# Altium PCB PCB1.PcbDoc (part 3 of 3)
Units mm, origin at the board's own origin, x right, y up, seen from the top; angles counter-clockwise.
Board outline 131.32 x 71.5 mm, 4 copper layers (Top Layer, Layer 1, Layer 2, Bottom Layer), stack 0.603 mm thick; 122 components, 132 nets, 671 pads, 444 vias.
Unrouted connection lines stored in the file: 1.
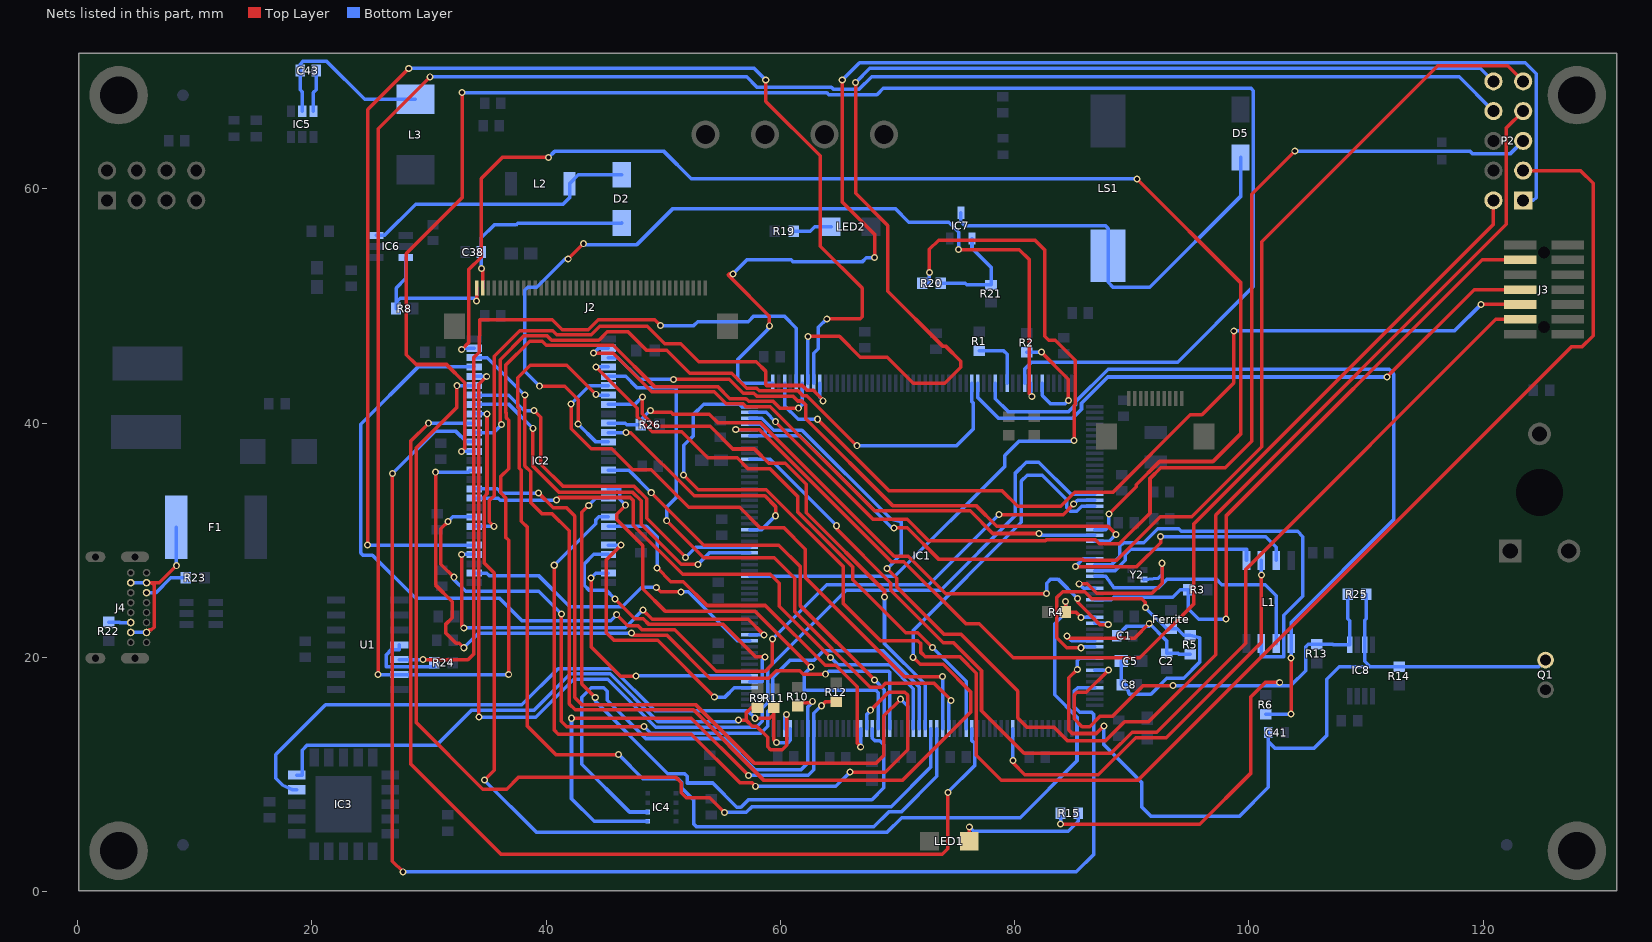
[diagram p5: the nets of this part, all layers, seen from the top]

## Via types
v1: diameter 0.6, hole 0.35, Top Layer to Bottom Layer, 444 vias

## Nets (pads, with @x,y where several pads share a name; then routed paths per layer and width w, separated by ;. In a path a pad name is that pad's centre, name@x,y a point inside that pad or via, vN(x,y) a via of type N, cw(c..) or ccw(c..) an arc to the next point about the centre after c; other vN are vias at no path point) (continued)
NetC41_2: C41.2 IC1.44 IC8.3 Q1.2 R14.2 R25.2 | length 72.5
  Top Layer w0.3: v1(85.344,18.974) 84.626,18.256 84.626,13.808 84.927,13.507 86.973,13.507 v1(87.613,14.148)
  Bottom Layer w0.3: v1(85.344,18.974) 85.344,19.716 85.547,19.919 IC1.44@86.841,19.919 ; v1(87.613,14.148) 87.613,12.564 90.83,9.347 90.83,7.239 91.643,6.426 99.162,6.426 101.652,8.917 101.652,12.826 ; C41.2@101.652,13.589 101.652,12.826 ; R25.2@110.02,25.4 110.02,23.292 109.893,23.165 IC8.3@109.893,21.09 109.893,19.66 110.338,19.215 ; Q1.2@125.316,19.779 124.752,19.215 R14.2@112.838,19.215 110.338,19.215 ; 101.652,12.826 102.21,12.268 105.562,12.268 106.629,13.335 106.629,18.136 107.709,19.215 110.338,19.215
NetC43_1: C43.1 IC5.5 L3.1 | length 15.4
  Bottom Layer w0.3: IC5.5@19.177,66.631 19.177,68.275 18.995,68.457 C43.1@18.995,70.104 18.995,70.637 19.274,70.917 21.237,70.917 24.511,67.643 L3.1@28.829,67.643
NetC43_2: C43.2 IC5.6 | length 3.6
  Bottom Layer w0.3: IC5.6@20.127,66.631 20.127,68.224 20.375,68.472 C43.2@20.375,70.104
NetD2_2: D2.2 IC6.3 L2.2 | length 23.8
  Bottom Layer w0.3: IC6.3@25.514,56.035 26.204,56.035 28.871,58.702 41.441,58.702 41.997,59.258 L2.2@41.997,60.452 42.744,61.199 D2.2@46.449,61.199
NetD5_2: D5.2 IC7.3 LS1.2 | length 36.2
  Bottom Layer w0.3: IC7.3@75.405,57.963 75.405,57.226 75.761,56.871 87.724,56.871 87.978,56.617 LS1.2@87.978,54.288 87.978,52.025 88.392,51.611 91.542,51.611 99.281,59.35 D5.2@99.281,62.687
NetF1_1: F1.1 J4.A4 J4.A9 J4.B4 J4.B9 | length 13.9
  Top Layer w0.3: J4.A9@5.884,22.132 6.104,22.352 6.299,22.352 6.528,22.581 6.528,26.153 6.299,26.382 ; J4.A4@5.884,26.382 6.299,26.382 ; v1(8.426,27.832) 6.976,26.382 6.299,26.382
  Bottom Layer w0.3: J4.B4@4.534,22.132 J4.A9@5.884,22.132 ; J4.B9@4.534,26.382 J4.A4@5.884,26.382 ; v1(8.426,27.832) F1.1@8.426,31.115
NetIC1_32: IC1.32 Y2.3 | length 13.6
  Top Layer w0.3: v1(85.507,26.289) 86.204,26.289 87.017,25.476 91.719,25.476 92.583,26.34 v1(92.583,28.042)
  Bottom Layer w0.3: v1(85.507,26.289) 85.877,25.919 IC1.32@86.841,25.919 ; Y2.3@91.02,26.651 92.253,26.756 92.583,27.086 v1(92.583,28.042)
NetIC1_34: IC1.34 J3.12 R3.1 | length 56.5
  Top Layer w0.3: v1(98.044,23.266) 98.044,32.08 119.906,53.942 J3.12@123.151,53.942
  Bottom Layer w0.3: IC1.34@86.841,24.919 88.24,24.919 88.474,25.153 93.505,25.153 94.132,25.781 R3.1@94.831,25.781 94.831,24.143 95.707,23.266 v1(98.044,23.266)
NetIC1_46: IC1.46 IC8.1 R13.2 R15.1 R25.1 | length 68
  Top Layer w0.3: v1(83.922,5.766) 95.809,5.766 100.134,10.091 100.134,16.601 101.397,17.863 v1(102.623,17.863) ; v1(88.011,18.919) 86.111,17.019 85.306,17.019 85.076,16.789 85.076,14.771 85.75,14.097 86.411,14.097 87.274,14.96 88.326,14.96 90.969,17.602 v1(93.523,17.602)
  Bottom Layer w0.3: v1(83.922,5.766) 83.926,5.77 R15.1@83.926,6.698 ; IC1.46@86.841,18.919 v1(88.011,18.919) ; v1(93.523,17.602) v1@102.623,17.602 ; v1(102.623,17.863) v1@102.623,17.602 ; R25.1@108.42,25.4 108.42,23.312 108.593,23.139 IC8.1@108.593,21.09 107.193,21.09 107.163,21.12 R13.2@105.791,21.12 105.054,21.12 104.851,20.917 104.851,18.872 103.581,17.602 v1@102.623,17.602
NetIC1_97: IC1.97 IC4.4 R12.2 | length 44.2
  Top Layer w0.3: v1(42.164,14.808) 52.4,14.808 v1(57.277,9.931) ; v1(63.5,15.875) 63.843,16.218 R12.2@64.77,16.218
  Bottom Layer w0.3: v1(42.164,14.808) 42.164,7.95 44.108,6.006 IC4.4@48.678,6.006 ; v1(57.277,9.931) 62.382,9.931 62.853,10.402 62.853,15.228 v1(63.5,15.875)
NetIC1_98: IC1.98 IC4.3 R10.1 | length 43.1
  Top Layer w0.3: R10.1@61.468,15.837 61.768,16.137 62.538,16.137 62.657,16.256 v1(62.738,16.256)
  Bottom Layer w0.3: IC4.3@48.678,6.806 47.117,6.806 43.028,10.895 43.028,16.586 43.84,17.399 44.933,17.399 45.229,17.103 45.229,16.344 48.493,13.08 55.203,13.08 57.858,10.425 61.759,10.425 62.353,11.02 IC1.98@62.353,13.931 62.353,15.79 62.738,16.175 v1(62.738,16.256)
NetIC1_101: IC1.101 IC3.9 R11.2 | length 57
  Top Layer w0.3: v1(57.836,14.808) 59.08,14.808 59.436,15.164 ; R11.2@59.436,15.71 59.436,15.164 ; v1(59.665,12.725) 59.436,12.954 59.436,15.164
  Bottom Layer w0.3: IC3.9@18.7,8.71 18.339,8.71 17.475,9.119 16.916,9.677 16.916,11.709 21.167,15.96 37.927,15.96 41.015,19.047 45.696,19.047 49.274,15.469 57.175,15.469 v1(57.836,14.808) ; v1(59.665,12.725) 60.65,12.725 60.853,12.929 IC1.101@60.853,13.931
NetIC1_102: IC1.102 IC3.10 R9.1 | length 55.8
  Top Layer w0.3: v1(56.423,14.656) 57.099,14.656 ; R9.1@58.039,15.71 57.506,15.71 57.099,15.304 57.099,14.656 ; v1(60.528,15.113) 60.528,12.497 60.147,12.116 59.157,12.116 58.906,12.366 58.906,13.179 57.955,14.13 57.583,14.13 57.099,14.615 57.099,14.656
  Bottom Layer w0.3: IC3.10@18.7,9.96 19.177,9.96 19.177,12.09 19.609,12.522 30.658,12.522 33.645,15.51 38.975,15.51 42.062,18.597 45.458,18.597 49.552,14.503 56.423,14.503 v1(56.423,14.656) ; IC1.102@60.353,13.931 60.353,14.938 v1(60.528,15.113)
NetIC1_127: IC1.127 R20.1 | length 64.8
  Top Layer w0.3: v1(72.72,52.857) 72.72,54.839 73.508,55.626 81.737,55.626 82.575,54.788 82.575,47.422 82.906,47.092 83.464,47.092 85.182,45.374 85.182,41.621 85.065,41.504 v1(85.065,38.506)
  Bottom Layer w0.3: IC1.127@57.365,26.919 69.769,26.919 79.146,36.297 79.146,37.236 80.386,38.476 85.034,38.476 v1(85.065,38.506) ; R20.1@72.098,51.943 72.72,51.943 v1(72.72,52.857)
NetIC1_151: IC1.151 IC1.153 P2.9 | length 100.8
  Top Layer w0.3: v1(69.698,31.064) 70.831,31.064 73.533,28.362 85.788,28.362 85.855,28.296 88.697,28.296 92.414,32.012 95.127,32.012 101.092,37.978 101.092,55.474 116.129,70.51 122.083,70.51 P2.9@123.411,69.182
  Bottom Layer w0.3: IC1.151@57.365,38.919 58.682,38.919 ; IC1.153@57.365,39.919 58.276,39.919 58.725,39.47 58.725,38.962 58.682,38.919 ; v1(69.698,31.064) 69.496,31.064 61.641,38.919 58.682,38.919
NetIC1_152: IC1.152 P2.2 | length 95.3
  Top Layer w0.3: v1(56.185,39.446) 58.217,39.446 69.479,28.184 70.517,28.184 75.839,22.863 76.975,22.863 79.868,19.969 90.673,19.969 95.304,24.599 95.304,31.423 120.871,56.99 P2.2@120.871,59.022
  Bottom Layer w0.3: v1(56.185,39.446) 56.212,39.419 IC1.152@57.365,39.419
NetIC1_154: IC1.154 P2.7 | length 117.3
  Top Layer w0.3: v1(69.113,27.584) 69.943,26.754 69.943,26.018 73.998,21.963 75.435,21.963 80.264,17.133 80.264,14.834 81.077,14.021 83.383,14.021 84.497,12.907 87.774,12.907 89.378,14.51 91.425,14.51 97.155,20.24 97.155,32.156 121.971,56.972 121.971,65.202 P2.7@123.411,66.642
  Bottom Layer w0.3: IC1.154@57.365,40.419 58.412,40.419 59.424,39.407 61.837,39.407 69.445,31.799 70.323,31.58 70.323,28.794 v1(69.113,27.584)
NetIC1_155: IC1.155 P2.5 | length 99.2
  Top Layer w0.3: v1(59.569,40.125) 67.901,31.793 70.815,31.793 72.626,29.982 82.626,29.982 82.693,30.048 86.893,30.048 87.228,29.713 88.94,29.713 91.55,32.324 91.55,35.279 92.458,36.186 97.964,36.186 100.228,38.451 100.228,59.538 v1(103.911,63.221)
  Bottom Layer w0.3: IC1.155@57.365,40.919 58.776,40.919 v1(59.569,40.125) ; v1(103.911,63.221) 118.872,63.221 119.075,63.017 122.326,63.017 P2.5@123.411,64.102
NetIC1_156: IC1.156 P2.3 | length 140.7
  Top Layer w0.3: v1(51.74,35.56) 52.984,34.315 58.801,34.315 65.38,27.737 65.38,24.587 68.539,21.428 71.73,21.428 72,21.158 72,20.422 72.375,20.046 75.331,20.046 76.716,18.661 76.716,11.651 78.842,9.525 90.526,9.525 127.508,46.507 128.422,46.507 129.388,47.473 129.388,60.477 128.303,61.562 P2.3@123.411,61.562
  Bottom Layer w0.3: v1(51.74,35.56) 51.74,38.1 52.578,38.938 52.578,40.742 53.442,41.605 56.507,41.605 56.693,41.419 IC1.156@57.365,41.419
NetIC1_157: IC1.157 P2.1 | length 116.2
  Top Layer w0.3: v1(55.939,52.739) 55.618,52.739 55.533,52.654 55.694,52.493 59.061,49.126 v1(59.061,48.313) ; v1(65.278,69.291) 65.278,58.877 68.047,56.109 v1(68.047,54.127)
  Bottom Layer w0.3: v1(55.939,52.739) 57.145,53.944 60.924,53.944 61.107,53.761 66.965,53.761 67.332,54.127 v1(68.047,54.127) ; v1(59.061,48.313) 59.061,48.232 58.918,48.089 58.918,47.996 56.337,45.415 56.337,43.815 56.744,43.409 59.353,43.409 IC1.157@59.353,43.407 ; v1(65.278,69.291) 66.751,70.764 123.571,70.764 124.511,69.825 124.511,59.258 124.275,59.022 P2.1@123.411,59.022
NetIC1_161: IC1.161 U1.5 | length 68.7
  Top Layer w0.3: v1(29.489,19.812) 33.325,19.812 33.8,20.287 33.8,45.571 34.276,46.046 34.341,48.844 40.507,48.844 41.361,47.99 43.607,47.99 44.461,48.844 49.267,48.844 v1(49.775,48.336)
  Bottom Layer w0.3: U1.5@27.465,19.812 v1(29.489,19.812) ; v1(49.775,48.336) 52.603,48.336 52.939,48.672 57.251,48.672 57.727,49.148 60.321,49.148 61.353,48.117 IC1.161@61.353,43.407
NetIC1_162: IC1.162 P2.8 U1.6 | length 214.5
  Top Layer w0.3: v1(25.654,18.542) 25.654,65.126 v1(30.099,69.571) ; v1(36.805,18.542) 36.805,29.997 36.535,30.267 36.535,33.639 36.128,34.046 36.128,35.447 36.8,36.119 36.8,40.263 36.576,40.488 36.576,40.901 36.532,40.945 36.532,44.94 38.588,46.996 39.655,46.996 40.011,46.64 45.74,46.64 49.251,43.129 54.643,43.129 55.678,42.093 57.059,42.093 57.286,41.866 59.368,41.866 59.959,41.275 v1(61.544,41.275)
  Bottom Layer w0.3: v1(25.654,18.542) U1.6@27.465,18.542 v1(36.805,18.542) ; v1(30.099,69.571) 57.118,69.571 57.998,68.691 64.357,68.691 64.561,68.488 66.7,68.488 67.783,69.571 117.942,69.571 P2.8@120.871,66.642 ; v1(61.544,41.275) 61.853,41.584 IC1.162@61.853,43.407
NetIC1_163: IC1.163 P2.10 | length 102.9
  Top Layer w0.3: v1(62.353,47.415) 65.041,47.415 66.819,45.637 69.113,45.637 71.341,43.409 74.016,43.409 75.387,44.78 75.387,45.288 74.092,46.584 73.838,46.584 69.164,51.257 69.164,56.871 66.421,59.614 v1(66.421,69.088)
  Bottom Layer w0.3: IC1.163@62.353,43.407 v1(62.353,47.415) ; v1(66.421,69.088) 67.64,70.307 119.746,70.307 P2.10@120.871,69.182
NetIC1_197: IC1.197 R1.1 | length 5
  Bottom Layer w0.3: R1.1@76.962,46.19 79.045,46.19 79.353,45.882 IC1.197@79.353,43.407
NetIC1_203: IC1.203 R2.2 | length 10
  Top Layer w0.3: v1(82.283,46.063) 84.582,43.764 v1(84.582,41.935)
  Bottom Layer w0.3: R2.2@81.026,46.063 v1(82.283,46.063) ; IC1.203@82.353,43.407 82.353,42.367 83.08,41.64 84.287,41.64 v1(84.582,41.935)
NetIC7_1: IC7.1 R20.2 R21.2 | length 9
  Bottom Layer w0.3: R20.2@73.698,51.943 75.768,51.943 75.907,51.804 R21.2@77.978,51.804 77.978,53.315 76.355,54.938 IC7.1@76.355,55.763
NetJ4_A5: J4.A5 R23.2 | length 3.9
  Bottom Layer w0.3: J4.A5@5.884,25.532 6.69,25.532 7.955,26.797 R23.2@9.233,26.797
NetJ4_B5: J4.B5 R22.2 | length 1.9
  Bottom Layer w0.3: R22.2@2.667,23.025 3.556,23.025 3.599,22.982 J4.B5@4.534,22.982
NetLED1_2: LED1.2 R15.2 | length 11.7
  Top Layer w0.3: LED1.2@76.122,4.318 76.122,5.535 v1(76.124,5.537)
  Bottom Layer w0.3: v1(76.124,5.537) 76.505,5.156 84.562,5.156 85.426,6.02 R15.2@85.426,6.698
NetLED2_1: LED2.1 R19.1 | length 3.4
  Bottom Layer w0.3: R19.1@61.125,56.388 62.535,56.388 62.916,56.769 LED2.1@64.34,56.769
NetR24_2: R24.2 U1.4 | length 7.2
  Bottom Layer w0.3: U1.4@27.465,21.082 27.465,20.676 26.797,20.676 26.365,20.244 26.365,19.202 30.442,19.202 R24.2@30.442,19.558
QSPI_CLK: IC1.63 L1.6 | length 36.2
  Top Layer w0.3: v1(79.853,11.201) 79.853,10.999 80.874,9.978 87.143,9.978 90.325,13.16 92.941,13.16 101.059,21.278 v1(101.059,27.051)
  Bottom Layer w0.3: v1(79.853,11.201) IC1.63@79.853,13.931 ; v1(101.059,27.051) L1.6@101.059,28.282
QSPI_D0: IC1.29 L1.5 | length 14.9
  Bottom Layer w0.3: IC1.29@86.841,27.419 88.582,27.419 89.451,28.288 89.451,28.778 89.909,29.235 99.789,29.235 L1.5@99.789,28.282
QSPI_D1: IC1.30 L1.2 | length 21
  Bottom Layer w0.3: IC1.30@86.841,26.919 87.782,26.919 88.468,25.933 92.262,25.933 93.024,26.695 97.206,26.695 97.688,26.213 101.397,26.213 102.329,25.281 L1.2@102.329,21.182
QSPI_D2: IC1.28 L1.3 | length 33.8
  Bottom Layer w0.3: IC1.28@86.841,27.919 88.269,27.919 88.973,28.623 88.973,29.482 89.286,29.794 91.008,29.794 92.202,30.988 93.992,30.988 94.222,30.759 104.166,30.759 104.605,30.319 104.605,25.23 102.972,23.597 102.972,20.066 101.059,20.066 L1.3@101.059,21.182
QSPI_D3: IC1.27 L1.7 | length 21.9
  Top Layer w0.3: v1(85.188,27.762) 90.424,27.762 92.462,29.8 v1(92.462,30.308)
  Bottom Layer w0.3: v1(85.188,27.762) 85.845,28.419 IC1.27@86.841,28.419 ; v1(92.462,30.308) 101.441,30.308 102.329,29.421 L1.7@102.329,28.282
QSPI_NCS: IC1.195 L1.1 R6.2 | length 72.4
  Top Layer w0.3: v1(103.599,15.169) v1(103.599,19.964)
  Bottom Layer w0.3: IC1.195@78.353,43.407 78.353,42.094 79.451,40.996 84.607,40.996 85.192,41.58 85.192,41.819 87.975,44.602 111.963,44.602 112.37,44.196 112.37,31.775 103.599,23.005 L1.1@103.599,21.182 v1(103.599,19.964) ; R6.2@101.44,15.169 v1(103.599,15.169)
SDRAM_A0: IC1.16 IC2.23 | length 101
  Top Layer w0.3: v1(34.25,14.91) 34.25,43.321 v1(34.925,43.996)
  Bottom Layer w0.3: IC2.23@33.863,43.997 v1@34.924,43.997 ; v1(34.25,14.91) 39.116,14.91 42.342,18.136 45.263,18.136 49.352,14.046 57.937,14.046 58.445,14.554 58.445,15.665 58.909,16.129 58.909,19.031 65.624,25.746 73.674,25.746 80.065,32.137 80.065,35.752 80.977,36.663 82.066,36.663 84.811,33.919 IC1.16@86.841,33.919
SDRAM_A1: IC1.17 IC2.24 | length 97.3
  Top Layer w0.3: v1(46.025,23.647) 46.972,22.7 47.846,22.7 48.183,22.363 50.969,22.363 54.51,18.821 58.725,18.821 59.309,19.406 v1(59.309,21.559) ; v1(78.644,32.189) 84.132,32.189 v1(85.039,33.096)
  Bottom Layer w0.3: IC2.24@33.863,44.797 29.058,44.797 24.165,39.904 24.165,28.921 24.359,28.727 25.171,28.727 28.854,25.044 36.017,25.044 37.938,23.124 45.501,23.124 v1(46.025,23.647) ; v1(59.309,21.559) 63.946,26.196 72.651,26.196 v1(78.644,32.189) ; v1(85.039,33.096) 85.362,33.419 IC1.17@86.841,33.419
SDRAM_A2: IC1.18 IC2.25 | length 108.6
  Top Layer w0.3: v1(38.176,42.393) 38.176,36.347 38.684,35.839 38.684,33.223 39.624,32.283 40.488,32.283 41.961,30.81 41.961,16.027 42.469,15.519 52.578,15.519 58.598,9.5 70.398,9.5 76.266,15.367 76.266,17.028 73.889,19.406 71.933,19.406 v1(71.323,20.015)
  Bottom Layer w0.3: IC2.25@33.863,45.597 34.972,45.597 v1(38.176,42.393) ; v1(71.323,20.015) 71.323,22.276 80.575,31.527 80.575,35.058 81.077,35.56 82.347,35.56 84.43,33.477 84.43,32.791 84.734,32.487 85.293,32.487 85.725,32.919 IC1.18@86.841,32.919
SDRAM_A3: IC1.22 IC2.26 | length 116.3
  Top Layer w0.3: v1(32.791,46.279) 33.376,46.863 33.376,53.086 34.468,54.178 34.468,60.884 36.271,62.687 v1(40.208,62.687) ; v1(88.036,32.233) 90.373,34.569 90.373,34.738 92.364,36.728 96.926,36.728 99.314,39.116 99.314,51.968 v1(90.424,60.858)
  Bottom Layer w0.3: v1(32.791,46.279) 32.91,46.397 IC2.26@33.863,46.397 ; v1(40.208,62.687) 40.716,63.195 50.063,63.195 52.4,60.858 v1(90.424,60.858) ; IC1.22@86.841,30.919 87.782,30.919 88.036,31.173 v1(88.036,32.233)
SDRAM_A4: IC1.23 IC2.29 | length 50.7
  Top Layer w0.3: v1(44.044,45.974) 45.72,45.974 49.026,42.668 54.358,42.668 55.382,41.643 56.836,41.643 57.063,41.416 59.131,41.416 68.026,32.521 76.19,32.521 78.129,30.582 v1(82.076,30.582)
  Bottom Layer w0.3: v1(44.044,45.974) 44.467,46.397 IC2.29@45.319,46.397 ; v1(82.076,30.582) 82.239,30.419 IC1.23@86.841,30.419
SDRAM_A5: IC1.24 IC2.30 | length 52.3
  Top Layer w0.3: v1(50.876,43.739) 55.628,43.739 56.823,42.544 57.736,42.544 57.963,42.316 61.052,42.316 61.476,41.892 61.836,41.892 62.148,41.58 62.148,40.392 69.569,32.971 76.696,32.971 78.477,31.19 87.96,31.19 v1(88.645,30.505)
  Bottom Layer w0.3: IC2.30@45.319,45.597 46.126,45.597 47.985,43.739 v1(50.876,43.739) ; IC1.24@86.841,29.919 88.06,29.919 v1(88.645,30.505)
SDRAM_A6: IC1.71 IC2.31 | length 49.7
  Top Layer w0.3: v1(44.247,44.806) 47.769,41.284 47.769,40.549 49.055,39.263 51.57,39.263 53.791,37.042 56.311,37.042 57.265,36.088 59.131,36.088 61.497,33.723 61.497,32.393 66.168,27.721 66.168,26.642 70.7,22.11 71.724,22.11 v1(72.975,20.858)
  Bottom Layer w0.3: v1(44.247,44.806) 44.255,44.797 IC2.31@45.319,44.797 ; v1(72.975,20.858) 75.859,17.974 75.859,14.902 75.853,14.896 IC1.71@75.853,13.931
SDRAM_A7: IC1.74 IC2.32 | length 52.9
  Top Layer w0.3: v1(50.292,31.674) 53.467,28.499 59.487,28.499 61.214,26.772 61.214,23.922 67.666,17.47 68.64,17.47 68.95,17.78 73.127,17.78 v1(74.574,16.332)
  Bottom Layer w0.3: IC2.32@45.319,43.997 46.783,43.997 47.752,43.028 51.003,43.028 51.105,42.926 51.105,33.655 50.292,32.842 v1(50.292,31.674) ; IC1.74@74.353,13.931 74.353,16.111 v1(74.574,16.332)
SDRAM_A8: IC1.75 IC2.33 | length 52.3
  Top Layer w0.3: v1(42.136,41.643) 42.136,39.525 43.858,37.803 45.609,37.803 47.395,36.017 48.975,36.017 52.181,32.811 56.515,32.811 58.235,31.091 60.273,31.091 62.122,29.242 62.122,26.829 70.579,18.372 v1(73.853,18.372)
  Bottom Layer w0.3: v1(42.136,41.643) 43.691,43.197 IC2.33@45.319,43.197 ; IC1.75@73.853,13.931 v1(73.853,18.372)
SDRAM_A9: IC1.76 IC2.34 | length 85.2
  Top Layer w0.3: v1(44.242,42.466) 41.75,44.958 38.641,44.958 37.565,43.882 37.565,41.378 37.7,41.243 37.7,36.165 37.886,35.98 37.886,31.634 38.405,31.115 38.405,14.122 40.818,11.709 v1(46.184,11.709)
  Bottom Layer w0.3: v1(44.242,42.466) 44.311,42.397 IC2.34@45.319,42.397 ; v1(46.184,11.709) 48.26,9.633 51.276,9.633 51.597,9.313 51.597,8.831 52.58,7.847 52.58,5.795 52.832,5.543 67.982,5.543 69.248,6.809 70.309,6.809 73.353,9.853 IC1.76@73.353,13.931
SDRAM_A10: IC1.77 IC2.22 | length 85
  Top Layer w0.3: v1(32.385,43.197) 32.385,41.351 28.889,37.856 28.889,14.468 34.595,8.763 36.627,8.763 37.617,9.754 51.08,9.754 51.533,9.3 51.533,8.458 51.974,8.018 53.975,8.018 v1(55.22,6.773)
  Bottom Layer w0.3: v1(32.385,43.197) IC2.22@33.863,43.197 ; v1(55.22,6.773) 57.08,6.773 57.571,7.264 69.447,7.264 72.853,10.67 IC1.77@72.853,13.931
SDRAM_A11: IC1.78 IC2.35 | length 46.2
  Top Layer w0.3: v1(48.219,42.24) 48.219,40.797 49.29,39.726 54,39.726 55.931,37.795 57.785,37.795 59.002,36.578 60.424,36.578 62.203,34.8 62.203,32.359 68.885,25.677 v1(68.885,25.146)
  Bottom Layer w0.3: IC2.35@45.319,41.597 47.576,41.597 v1(48.219,42.24) ; v1(68.885,25.146) 68.885,21.184 72.353,17.715 IC1.78@72.353,13.931
SDRAM_BA0: IC1.131 IC2.20 | length 32.6
  Top Layer w0.3: v1(38.862,39.565) 38.862,36.347 41.097,34.112 47.374,34.112 48.108,33.379 48.108,31.363 51.525,27.946 v1(52.959,27.946)
  Bottom Layer w0.3: IC2.20@33.863,41.597 36.83,41.597 v1(38.862,39.565) ; v1(52.959,27.946) 53.932,28.919 IC1.131@57.365,28.919
SDRAM_BA1: IC1.132 IC2.21 | length 32.9
  Top Layer w0.3: v1(38.979,41.065) 39.549,40.495 39.549,36.503 41.457,34.595 47.528,34.595 48.579,33.544 48.579,31.876 v1(51.909,28.546)
  Bottom Layer w0.3: IC2.21@33.863,42.397 36.805,42.397 38.137,41.065 v1(38.979,41.065) ; v1(51.909,28.546) 52.782,29.419 IC1.132@57.365,29.419
SDRAM_CAS: IC1.191 IC2.17 | length 58.4
  Top Layer w0.3: v1(36.19,39.878) 36.082,39.986 36.082,45.43 38.099,47.446 40.105,47.446 40.461,47.09 44.507,47.09 45.22,47.803 46.99,47.803 48.565,46.228 50.292,46.228 52.249,44.271 55.848,44.271 57.125,42.994 57.959,42.994 58.186,42.766 61.502,42.766 61.926,42.342 62.255,42.342 v1(66.523,38.075)
  Bottom Layer w0.3: IC2.17@33.863,39.197 35.509,39.197 v1(36.19,39.878) ; v1(66.523,38.075) 75.035,38.075 76.479,39.518 76.479,41.711 76.353,41.836 IC1.191@76.353,43.407
SDRAM_CKE: IC1.38 IC2.37 R26.2 | length 54.1
  Top Layer w0.3: v1(48.895,41.097) 48.895,40.919 50.673,40.919 50.825,40.767 53.924,40.767 54.635,40.056 58.293,40.056 69.698,28.651 70.924,28.651 74.124,25.451 v1(82.728,25.451) ; v1(85.369,25.019) 85.369,24.714 87.274,22.809 v1(87.986,22.809)
  Bottom Layer w0.3: IC2.37@45.319,39.997 46.753,39.997 46.872,39.878 R26.2@48.095,39.878 48.095,40.297 v1(48.895,41.097) ; v1(82.728,25.451) 82.728,26.34 83.083,26.695 83.693,26.695 v1(85.369,25.019) ; IC1.38@86.841,22.919 87.876,22.919 v1(87.986,22.809)
SDRAM_CLK: IC1.135 IC2.38 | length 20.4
  Top Layer w0.3: v1(46.813,39.197) 47.219,39.197 52.628,33.788 58.68,33.788 59.583,32.885 v1(59.583,32.098)
  Bottom Layer w0.3: IC2.38@45.319,39.197 v1(46.813,39.197) ; IC1.135@57.365,30.919 58.404,30.919 v1(59.583,32.098)
SDRAM_CS: IC1.37 IC2.19 R4.2 | length 106.5
  Top Layer w0.3: v1(34.722,9.525) 35.56,10.363 35.56,27.203 34.7,28.063 34.7,33.731 34.95,33.981 v1(34.95,40.797) ; v1(84.353,24.79) 84.366,24.778 R4.2@84.366,23.876 85.217,23.876 v1(85.674,23.419)
  Bottom Layer w0.3: IC2.19@33.863,40.797 v1(34.95,40.797) ; v1(34.722,9.525) 39.154,5.093 69.126,5.093 70.358,6.325 80.475,6.325 85.319,11.168 85.319,14.908 83.405,16.822 83.405,22.875 84.353,23.824 v1(84.353,24.79) ; v1(85.674,23.419) IC1.37@86.841,23.419
SDRAM_D0: IC1.116 IC2.2 | length 27.3
  Top Layer w0.3: v1(49.403,25.984) 49.784,25.603 v1(51.511,25.603)
  Bottom Layer w0.3: IC2.2@33.863,27.197 34.944,27.197 35.15,26.991 39.346,26.991 42.004,24.333 46.507,24.333 48.158,25.984 v1(49.403,25.984) ; v1(51.511,25.603) 52.128,25.603 56.312,21.419 IC1.116@57.365,21.419
SDRAM_D1: IC1.117 IC2.4 | length 35.8
  Top Layer w0.3: v1(32.791,28.804) 32.791,22.708 v1(32.969,22.53) ; v1(48.261,24.053) 49.047,23.266 57.25,23.266 v1(58.598,21.919)
  Bottom Layer w0.3: v1(32.791,28.804) 32.798,28.797 IC2.4@33.863,28.797 ; v1(32.969,22.53) 46.737,22.53 v1(48.261,24.053) ; IC1.117@57.365,21.919 v1(58.598,21.919)
SDRAM_D2: IC1.164 IC2.5 | length 114.8
  Top Layer w0.3: v1(24.765,29.597) 24.765,66.777 v1(28.27,70.282) ; v1(58.748,69.291) 58.748,67.465 63.398,62.814 63.398,55.118 66.98,51.537 66.98,49.098 66.777,48.895 v1(63.957,48.895)
  Bottom Layer w0.3: v1(24.765,29.597) IC2.5@33.863,29.597 ; v1(28.27,70.282) 57.757,70.282 v1(58.748,69.291) ; IC1.164@62.853,43.407 62.853,45.981 63.236,46.365 63.236,48.174 v1(63.957,48.895)
SDRAM_D3: IC1.165 IC2.7 | length 50.9
  Top Layer w0.3: v1(35.537,31.197) 35.15,31.584 35.15,33.397 35.56,33.807 35.56,45.714 37.742,47.896 40.555,47.896 40.911,47.54 43.84,47.54 44.56,48.26 48.641,48.26 50.109,46.792 51.486,46.792 53.026,45.252 57.921,45.252 58.764,44.41 58.764,43.265 58.812,43.216 61.878,43.216 62.302,42.792 62.835,42.792 63.145,42.482 63.145,42.473 63.627,41.991 v1(63.627,41.91)
  Bottom Layer w0.3: IC2.7@33.863,31.197 v1(35.537,31.197) ; IC1.165@63.353,43.407 63.353,42.224 63.627,41.95 v1(63.627,41.91)
SDRAM_D4: IC1.79 IC2.8 | length 68.5
  Top Layer w0.3: v1(31.623,31.598) 31.013,30.988 31.013,27.965 v1(32.131,26.848) ; v1(41.3,23.724) 41.3,14.554 41.758,14.097 v1(48.362,14.097)
  Bottom Layer w0.3: v1(31.623,31.598) 32.022,31.997 IC2.8@33.863,31.997 ; v1(32.131,26.848) 32.131,26.645 33.122,25.654 39.37,25.654 v1(41.3,23.724) ; v1(48.362,14.097) 48.92,13.538 58.318,13.538 58.903,14.123 58.903,15.418 59.36,15.875 59.36,18.288 60.849,19.777 62.875,19.777 63.687,20.59 68.742,20.59 71.853,17.479 IC1.79@71.853,13.931
SDRAM_D5: IC1.80 IC2.10 | length 50.2
  Top Layer w0.3: v1(40.869,33.426) 41.097,33.655 47.193,33.655 47.447,33.401 47.447,31.296 51.654,27.089 59.142,27.089 59.892,26.34 59.892,24.385 v1(64.287,19.99)
  Bottom Layer w0.3: IC2.10@33.863,33.597 35.923,33.597 36.093,33.426 v1(40.869,33.426) ; v1(64.287,19.99) 64.915,19.362 69.334,19.362 71.353,17.342 IC1.80@71.353,13.931
SDRAM_D6: IC1.81 IC2.11 | length 62.2
  Top Layer w0.3: v1(39.345,34.036) 40.615,32.766 41.739,32.766 42.433,32.072 42.433,16.581 43.033,15.981 52.755,15.981 57.789,10.947 68.148,10.947 68.834,11.633 68.834,15.011 v1(70.256,16.434)
  Bottom Layer w0.3: IC2.11@33.863,34.397 35.831,34.397 36.192,34.036 v1(39.345,34.036) ; v1(70.256,16.434) 70.859,15.831 70.859,14.908 70.853,14.902 IC1.81@70.853,13.931
SDRAM_D7: IC1.84 IC2.13 | length 63.8
  Top Layer w0.3: v1(30.556,35.814) 30.556,26.187 31.979,24.765 31.979,23.393 31.445,22.86 31.445,22.073 32.309,21.209 32.588,21.209 v1(32.969,20.828) ; v1(47.269,22.073) 47.429,21.913 50.292,21.913 53.968,18.237 59.004,18.237 59.639,18.872 61.646,18.872 61.951,18.567 v1(63.856,18.567)
  Bottom Layer w0.3: v1(30.556,35.814) 33.345,35.814 33.528,35.997 IC2.13@33.863,35.997 ; v1(32.969,20.828) 34.188,22.047 47.244,22.047 v1(47.269,22.073) ; v1(63.856,18.567) 64.117,18.829 69.23,18.829 69.353,18.706 IC1.84@69.353,13.931
SDRAM_D8: IC1.85 IC2.42 | length 36.6
  Top Layer w0.3: v1(48.971,34.061) 53.442,29.591 59.866,29.591 61.672,27.785 61.672,24.438 v1(68.04,18.07)
  Bottom Layer w0.3: IC2.42@45.319,35.997 47.036,35.997 v1(48.971,34.061) ; v1(68.04,18.07) 68.853,17.258 IC1.85@68.853,13.931
SDRAM_D9: IC1.86 IC2.44 | length 39.8
  Top Layer w0.3: v1(46.787,32.995) 46.025,32.233 46.025,31.775 48.245,29.556 48.245,25.873 50.19,23.927 57.861,23.927 v1(62.611,19.177)
  Bottom Layer w0.3: IC2.44@45.319,34.397 46.279,34.397 46.279,33.503 v1(46.787,32.995) ; v1(62.611,19.177) 62.024,18.59 62.024,17.218 68.127,17.218 68.353,16.992 IC1.86@68.353,13.931
SDRAM_D10: IC1.87 IC2.45 | length 54.5
  Top Layer w0.3: v1(43.637,32.987) 43.037,32.387 43.037,17.735 v1(44.191,16.581)
  Bottom Layer w0.3: v1(43.637,32.987) 44.247,33.597 IC2.45@45.319,33.597 ; v1(44.191,16.581) 44.191,16.286 50.394,10.083 51.816,10.083 52.047,9.852 52.047,9.281 54.217,9.281 56.274,7.223 56.632,7.223 57.275,7.865 67.814,7.865 68.824,8.875 68.824,12.532 68.478,12.878 68.072,12.878 67.853,13.097 IC1.87@67.853,13.931
SDRAM_D11: IC1.88 IC2.47 | length 64.3
  Top Layer w0.3: v1(40.691,27.871) 40.691,13.803 41.046,13.447 52.395,13.447 56.521,9.322 57.566,9.322 v1(57.887,9.001) ; v1(65.938,10.211) 68.961,10.211 70.859,12.109 70.859,16.789 70.615,17.034 69.231,17.034 v1(67.691,15.494)
  Bottom Layer w0.3: v1(40.691,27.871) 44.24,31.42 44.24,31.736 44.501,31.997 IC2.47@45.319,31.997 ; v1(57.887,9.001) 64.729,9.001 v1(65.938,10.211) ; IC1.88@67.353,13.931 67.353,15.118 67.691,15.457 v1(67.691,15.494)
SDRAM_D12: IC1.89 IC2.48 | length 35.3
  Top Layer w0.3: v1(49.471,27.642) 50.646,26.467 51.7,26.467 53.733,24.435 58.713,24.435 63.83,19.318 64.731,19.318 66.548,17.501 66.548,12.696 66.853,12.391 v1(66.853,12.37)
  Bottom Layer w0.3: IC2.48@45.319,31.197 48.565,31.197 49.471,30.29 v1(49.471,27.642) ; v1(66.853,12.37) IC1.89@66.853,13.931
SDRAM_D13: IC1.108 IC2.50 | length 23.9
  Top Layer w0.3: v1(46.406,29.597) 45.133,28.324 45.133,22.12 45.79,21.463 49.512,21.463 v1(54.354,16.621)
  Bottom Layer w0.3: IC2.50@45.319,29.597 v1(46.406,29.597) ; v1(54.354,16.621) 55.27,16.621 56.068,17.419 IC1.108@57.365,17.419
SDRAM_D14: IC1.109 IC2.51 | length 25.5
  Top Layer w0.3: v1(45.865,25.001) 47.569,23.297 48.296,23.297 48.776,22.816 55.111,22.816 57.887,20.041 v1(58.699,20.041)
  Bottom Layer w0.3: IC2.51@45.319,28.797 44.062,28.797 43.24,27.975 43.24,26.168 43.653,25.756 45.11,25.756 v1(45.865,25.001) ; IC1.109@57.365,17.919 58.459,17.919 58.459,19.8 v1(58.699,20.041)
SDRAM_D15: IC1.110 IC2.53 | length 22.1
  Top Layer w0.3: v1(43.84,26.797) 43.84,20.892 46.317,18.415 v1(47.676,18.415)
  Bottom Layer w0.3: v1(43.84,26.797) 44.24,27.197 IC2.53@45.319,27.197 ; v1(47.676,18.415) 47.68,18.419 IC1.110@57.365,18.419
SDRAM_LDQM: IC1.200 IC2.15 | length 145.7
  Top Layer w0.3: v1(32.766,37.597) 33.044,37.875 33.044,43.461 31.496,45.009 28.905,45.009 28.067,45.847 28.067,54.483 32.817,59.233 v1(32.817,68.224)
  Bottom Layer w0.3: v1(32.766,37.597) IC2.15@33.863,37.597 ; v1(32.817,68.224) 63.932,68.224 64.118,68.038 68.241,68.038 68.783,68.58 100.178,68.58 100.381,68.377 100.381,51.664 93.929,45.212 81.437,45.212 80.853,44.628 IC1.200@80.853,43.407
SDRAM_RAS: IC1.70 IC2.18 | length 94.2
  Top Layer w0.3: v1(29.972,39.997) 28.423,38.448 28.423,10.922 36.144,3.2 73.812,3.2 74.295,3.683 v1(74.295,8.484)
  Bottom Layer w0.3: v1(29.972,39.997) IC2.18@33.863,39.997 ; v1(74.295,8.484) 76.581,10.77 76.581,12.675 76.353,12.903 IC1.70@76.353,13.931
SDRAM_UDQM: IC1.201 IC2.39 | length 79.4
  Top Layer w0.3: v1(39.446,43.155) 41.592,43.155 42.736,42.01 v1(42.736,39.915) ; v1(41.885,54.026) v1(43.18,55.321) ; v1(75.209,54.813) 80.391,54.813 81.229,53.975 81.229,42.52 v1(81.458,42.291)
  Bottom Layer w0.3: v1(39.446,43.155) 38.168,44.433 38.168,51.343 38.418,51.593 39.198,51.593 41.631,54.026 v1(41.885,54.026) ; v1(42.736,39.915) 44.255,38.397 IC2.39@45.319,38.397 ; v1(43.18,55.321) 43.252,55.249 47.752,55.249 50.827,58.324 69.803,58.324 70.96,57.166 74.355,57.166 75.209,56.312 v1(75.209,54.813) ; IC1.201@81.353,43.407 81.353,42.396 v1(81.458,42.291)
SDRAM_WE: IC1.49 IC2.16 | length 119.9
  Top Layer w0.3: v1(26.873,35.687) 26.873,2.616 v1(27.788,1.702)
  Bottom Layer w0.3: v1(26.873,35.687) 30.48,39.294 32.309,39.294 33.206,38.397 IC2.16@33.863,38.397 ; v1(27.788,1.702) 85.268,1.702 86.766,3.2 86.766,15.103 86.563,15.307 85.557,15.307 85.065,15.799 85.065,17.114 85.369,17.419 IC1.49@86.841,17.419
SWCLK: IC1.159 J3.6 | length 78
  Top Layer w0.3: v1(63.17,40.335) 69.293,34.212 78.942,34.212 80.252,32.902 83.931,32.902 85.141,34.112 88.392,34.112 94.996,40.716 95.987,40.716 98.704,43.434 v1(98.704,47.879) ; v1(119.804,50.132) J3.6@123.151,50.132
  Bottom Layer w0.3: IC1.159@60.353,43.407 60.353,41.501 61.519,40.335 v1(63.17,40.335) ; v1(98.704,47.879) 117.551,47.879 v1(119.804,50.132)
SWDIO: IC1.147 J3.4 | length 97.7
  Top Layer w0.3: v1(64.795,31.242) 64.795,30.967 69.423,26.339 69.423,25.749 73.912,21.26 74.778,21.26 77.166,18.872 77.166,15.443 80.797,11.811 88.222,11.811 90.021,13.61 92.121,13.61 99.72,21.209 99.72,27.508 121.074,48.862 J3.4@123.151,48.862
  Bottom Layer w0.3: IC1.147@57.365,36.919 59.118,36.919 v1(64.795,31.242)
SWO: IC1.192 J3.8 | length 53.1
  Top Layer w0.3: v1(111.768,43.942) 119.228,51.402 J3.8@123.151,51.402
  Bottom Layer w0.3: IC1.192@76.853,43.407 76.853,42.189 78.605,40.437 84.967,40.437 85.703,41.173 85.703,41.694 87.951,43.942 v1(111.768,43.942)
VDDA: C5.1 C8.2 Ferrite.2 IC1.42 R5.2 | length 33.9
  Top Layer w0.3: v1(85.674,20.828) 84.43,20.828 83.591,21.666 83.591,25.121 84.09,25.619 85.974,25.619 86.574,25.019 90.856,25.019 91.161,24.714 v1(91.161,24.257)
  Bottom Layer w0.3: v1(85.674,20.828) 85.765,20.919 IC1.42@86.841,20.919 ; C5.1@89.089,19.685 89.089,18.654 89.099,18.644 C8.2@89.099,17.653 89.51,17.653 89.764,16.858 91.634,16.858 92.996,18.22 94.42,18.22 95.809,19.609 95.809,21.666 R5.2@94.996,21.882 94.437,21.882 93.878,22.441 Ferrite.2@93.345,22.441 92.977,22.441 v1(91.161,24.257)
VLED+: C38.2 D2.1 J2.2 | length 16.9
  Top Layer w0.3: v1(34.472,53.2) 34.567,53.105 J2.2@34.567,51.529
  Bottom Layer w0.3: v1(34.472,53.2) C38.2@34.472,54.61 34.472,55.833 35.56,56.921 37.423,56.921 37.576,57.074 46.449,57.074 D2.1@46.449,57.099
VLED–: IC6.6 J2.1 R8.2 | length 12.9
  Top Layer w0.3: v1(34.061,50.444) 34.067,50.45 J2.1@34.067,51.529
  Bottom Layer w0.3: R8.2@27.19,49.784 27.19,50.317 ; IC6.6@28.014,54.135 28.014,52.361 27.19,51.537 27.19,50.317 ; v1(34.061,50.444) 33.846,50.66 27.533,50.66 27.19,50.317
VREF+: C1.2 C2.2 IC1.41 R5.1 | length 18.9
  Top Layer w0.3: v1(84.455,21.825) 84.455,21.652 90.232,21.652 v1(91.491,22.911)
  Bottom Layer w0.3: v1(84.455,21.825) 84.852,21.428 86.274,21.428 86.274,21.419 IC1.41@86.841,21.419 ; C1.2@88.718,21.844 88.748,21.844 89.586,22.682 91.491,22.682 v1(91.491,22.911) 92.964,21.438 C2.2@92.964,20.375 93.929,20.375 94.022,20.282 R5.1@94.996,20.282
pads on no net: IC1.1 IC1.2 IC1.6 IC1.7 IC1.8 IC1.13 IC1.19 IC1.20 IC1.31 IC1.33 IC1.36 IC1.43 IC1.45 IC1.47 IC1.48 IC1.53 IC1.54 IC1.56 IC1.64 IC1.67 IC1.68 IC1.69 IC1.95 IC1.96 IC1.99 IC1.100 IC1.104 IC1.105 IC1.106 IC1.107 IC1.111 IC1.112 IC1.113 IC1.118 IC1.119 IC1.120 IC1.121 IC1.122 IC1.123 IC1.126 IC1.128 IC1.129 IC1.130 IC1.134 IC1.138 IC1.141 IC1.142 IC1.146 IC1.160 IC1.166 IC1.168 IC1.169 IC1.173 IC1.174 IC1.175 IC1.176 IC1.177 IC1.178 IC1.186 IC1.187 IC1.193 IC1.194 IC1.196 IC1.206 IC1.207 IC1.208 IC2.36 IC2.40 IC3.1 IC3.2 IC3.3 IC3.4 IC3.5 IC3.8 IC3.11 IC3.12 IC3.13 IC3.14 IC3.15 IC3.16 IC3.17 IC3.18 IC8.7 J3.1 J3.2 J3.9 J3.10 J3.13 J3.14 J3.15 J3.16 J4.A8 J4.B8 J15.3 J15.5 J15.7 L1.4 P1.3 P1.4 P1.5 U1.2 U1.3 U1.7 U1.8 U1.9 U1.10 VR1.MH1

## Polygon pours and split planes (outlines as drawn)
GND on Layer 1 (split plane): 130.902,0.604 0.604,0.604 0.604,71.085 130.902,71.085
3V3 on Layer 2 (split plane): 130.902,0.604 0.604,0.604 0.604,71.085 130.902,71.085

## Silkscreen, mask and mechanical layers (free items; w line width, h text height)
Top Overlay:
  lines w0.254: 1.016,37.592 11.557,37.592 11.557,56.769 1.016,56.769 1.016,37.592 ; 12.192,3.429 117.612,3.429 117.612,70.499 12.192,70.499 12.192,3.429
  text "Display 4\"3" at 62.865,51.975 h1.52
Mechanical 1:
  lines w0.254: -0.016,-4.577 -0.017,-4.069 ; 1.507,-3.813 -0.016,-4.323 ; 1.508,-4.829 -0.016,-4.323 ; 57.174,-4.268 -0.016,-4.323 ; 74.238,-4.251 131.429,-4.196 ; 129.904,-3.689 131.429,-4.196 ; 129.905,-4.705 131.429,-4.196 ; 131.429,-4.45 131.428,-3.942 ; 134.577,69.994 135.079,71.52 ; 134.82,1.795 135.333,0.273 ; 134.825,71.519 135.333,71.521 ; 135.079,0.272 135.587,0.274 ; 135.178,43.793 135.079,71.52 ; 135.234,28 135.333,0.273 ; 135.593,69.998 135.079,71.52 ; 135.836,1.799 135.333,0.273
  text "71.247 (mm)" at 134.265,43.536 h1.52 r270.2
  text "131.445 (mm)" at 57.429,-5.181 h1.52 r0.06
